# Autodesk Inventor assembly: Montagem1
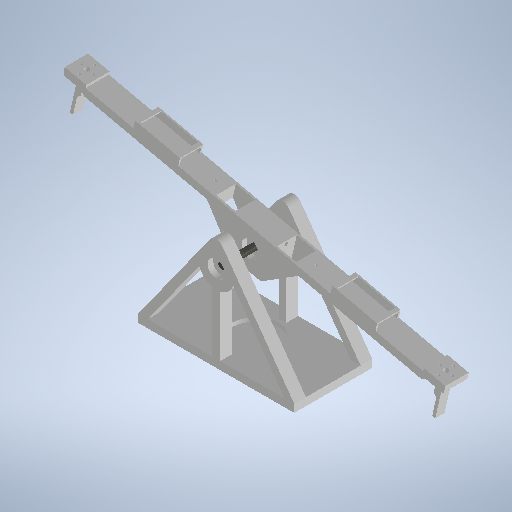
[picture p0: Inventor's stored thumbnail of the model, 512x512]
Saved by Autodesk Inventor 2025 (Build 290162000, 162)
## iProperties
Created: 2025-03
Part Number: Montagem1
Document SubType Name: Assembly
Designer: Ian
Author: Ian
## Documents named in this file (4)
- C:\Users\Ian\Desktop\Drone\BaseTestes\Cad1\Montagem1.iam
- C:\Users\Ian\Desktop\Drone\BaseTestes\Cad1\BaseMotor\Eixo.ipt
- C:\Users\Ian\Desktop\Drone\BaseTestes\Cad1\BaseMotor\EncaixeBase.ipt
- C:\Users\Ian\Desktop\Drone\BaseTestes\Cad1\BaseMotor\eixoBase.ipt
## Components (4 placed, 3 different names)
1. EncaixeBase:1 — Coincidente:5, Coincidente:6, Alinhado:2, Alinhado:3
2. eixoBase:1 — Coincidente:6, Coincidente:10, Alinhado:2, Alinhado:3
3. Eixo:1 — Coincidente:7, Coincidente:8, Coincidente:9, Coincidente:10
4. Eixo:2 — Coincidente:7, Coincidente:8, Coincidente:9
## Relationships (8: Mate 6, Flush 2)
- Coincidente:5 [Mate]: EncaixeBase:1
- Coincidente:6 [Mate]: EncaixeBase:1 ↔ eixoBase:1
- Coincidente:7 [Mate]: Eixo:1 ↔ Eixo:2
- Coincidente:8 [Mate]: Eixo:1 ↔ Eixo:2
- Coincidente:9 [Mate]: Eixo:1 ↔ Eixo:2
- Coincidente:10 [Mate]: eixoBase:1 ↔ Eixo:1
- Alinhado:2 [Flush]: EncaixeBase:1 ↔ eixoBase:1
- Alinhado:3 [Flush]: EncaixeBase:1 ↔ eixoBase:1
